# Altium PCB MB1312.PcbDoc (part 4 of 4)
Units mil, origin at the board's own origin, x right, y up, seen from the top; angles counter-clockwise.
Board outline 2755.91 x 5249.6 mil, 6 copper layers (Top Layer, GND, Signal, PWR, GND (Mid2), Bottom Layer), stack 74.545 mil thick; 297 components, 280 nets, 1142 pads, 623 vias.
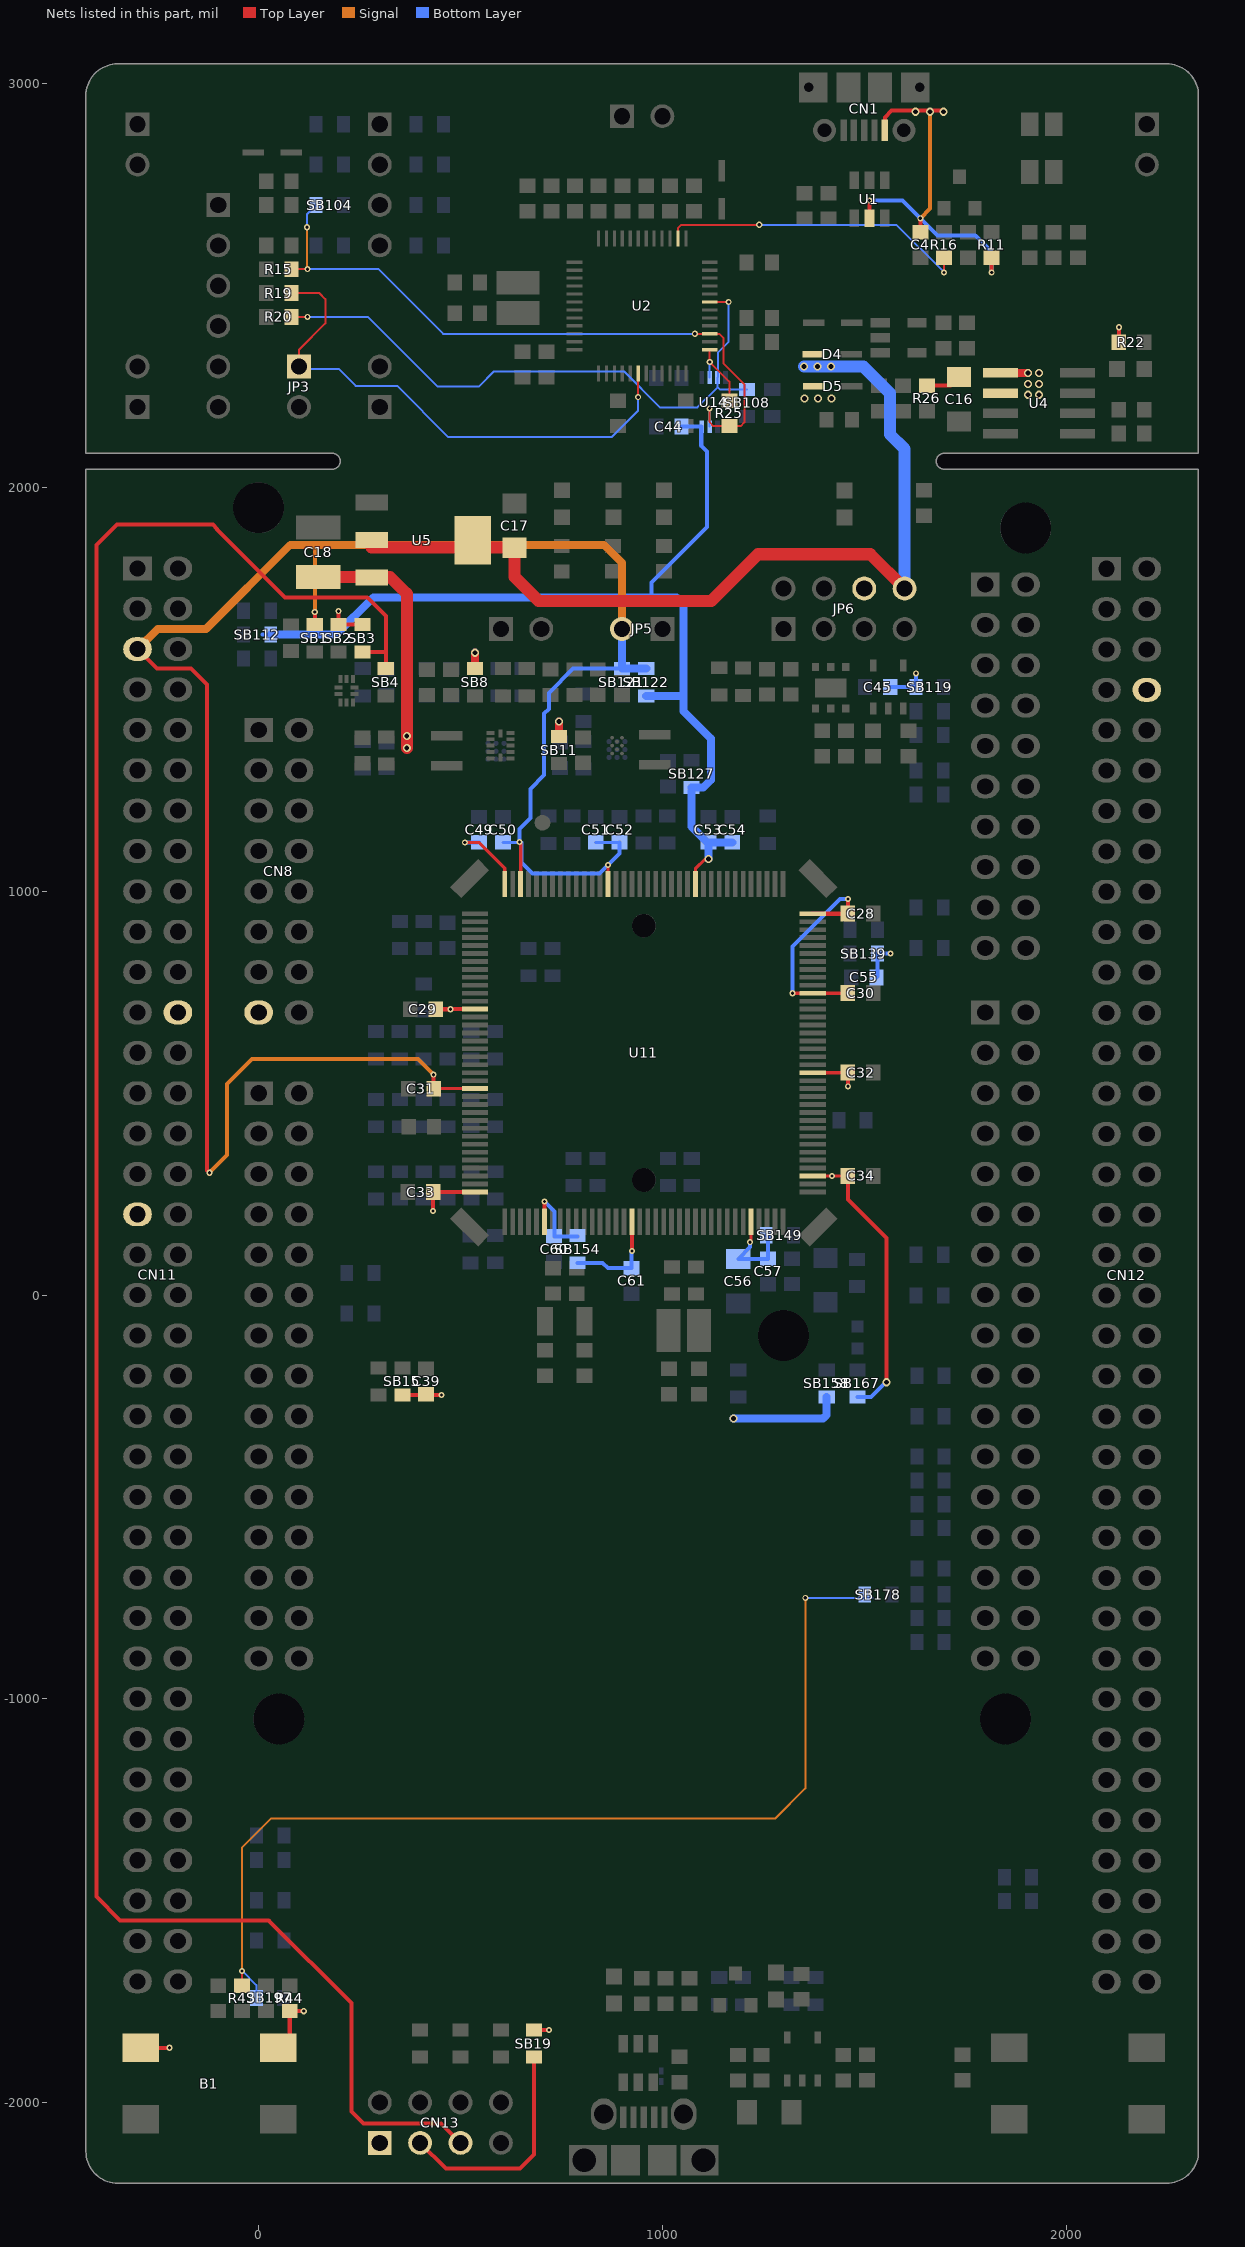
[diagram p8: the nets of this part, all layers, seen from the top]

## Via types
v1: diameter 15, hole 8, Top Layer to Bottom Layer, tented both sides, 405 vias
v2: diameter 16, hole 8, Top Layer to Bottom Layer, tented both sides, 179 vias
v3: diameter 20, hole 12, Top Layer to Bottom Layer, tented both sides, 39 vias

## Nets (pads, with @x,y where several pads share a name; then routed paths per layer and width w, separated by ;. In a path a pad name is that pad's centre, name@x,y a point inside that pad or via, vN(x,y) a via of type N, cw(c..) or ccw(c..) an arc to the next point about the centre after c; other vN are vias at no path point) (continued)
T_JTMS: R15.2 R25.2 SB104.1 U2.27 U14.7 | length 1711.1
  Top Layer w5: R15.2@81.5,2541 v1(121,2541) ; v1@1080.25,2381 v1(1080.35,2381.1) U2.27@1117.32,2381.1 1140.9,2381.1 1151,2371 1151,2308 1203,2256 1203,2161.47 1194.03,2152.5 R25.2@1166,2152.5 1126.5,2152.5 1117,2162 v1(1117,2196)
  Signal w5: v1@120,2542 v1(120,2645)
  Bottom Layer w5: v1(120,2645) 120,2677.75 SB104.1@142.25,2700 ; v1(121,2541) 297,2541 456.9,2381.1 v1(1080.35,2381.1) ; v1(1117,2196) 1117.16,2195.84 U14.7@1117.16,2150.98
T_NRST: JP3.1 R19.2 U2.18 | length 1318.5
  Top Layer w5: R19.2@81.5,2482 150,2482 165,2467 165,2407 100,2342 JP3.1@100,2300 ; v1(940,2224) 940.16,2224.16 U2.18@940.16,2282.68
  Bottom Layer w5: JP3.1@100,2300 100,2294.3 198.22,2294.3 240.37,2252.15 342.85,2252.15 470,2125 874,2125 940,2191 v1(940,2224)
T_SWDIO_IN: R25.1 U2.25 U14.2 | length 184.4
  Top Layer w5: U2.25@1117.32,2341.73 v1(1117.32,2310.97) 1166,2262.3 R25.1@1166,2215.5
  Bottom Layer w5: U14.2@1117.16,2273.02 1117.16,2310.81 v1(1117.32,2310.97)
T_SWO: R20.2 SB108.2 U2.31 U14.3 | length 1543.9
  Top Layer w5: R20.2@81.5,2423 v1(121,2423) ; U2.31@1117.32,2459.84 v1(1164.16,2459.84)
  Bottom Layer w5: v1(121,2423) 270.69,2423 442.69,2251 546,2251 583,2288 905,2288 994,2199 1086.84,2199 1136.84,2249 ; v1(1164.16,2459.84) 1164.16,2361.16 1137.32,2334.32 1137.32,2273.5 U14.3@1136.84,2273.02 1136.84,2249 ; SB108.2@1210,2243.5 1142.34,2243.5 1136.84,2249
U5V: C4.2 C16.1 CN1.1 CN12.8 D5.1 JP6.6 R11.2 R22.1 R26.1 U1.5 U4.1 U4.2 | length 1171.5
  Top Layer w10: U1.5@1513,2666.76 v1(1513,2711) ; CN1.1@1551.18,2885 1551.18,2917.18 1568,2934 v3@1696,2934 ; C4.2@1639,2632.5 v1(1639,2667) ; R26.1@1655,2252.5 1713.5,2252.5 C16.1@1735,2274 ; v1(1815.7,2533) R11.2@1815.7,2569.5 ; R22.1@2130.5,2360 v2@2130.5,2396.5
  Top Layer w20: U4.1@1837.53,2284 v3@1905.25,2284
  Signal w10: v1(1639,2667) 1663,2691 v3(1663,2931)
  Bottom Layer w10: v1(1513,2711) 1595,2711 v1(1639,2667) 1681,2625 1775,2625 1815.7,2584.3 v1@1815.7,2537.3 ; v3(1696,2931) v3@1696,2934
  other v2: 2131,2397
  other v3: 1352,2221 1385.5,2221 1419,2221 1906,2230 1933,2230 1906,2257 1933,2257 1906,2284 1933,2284 1627,2931
USB_RENUMN: R16.2 U2.38 | length 773.2
  Top Layer w5: U2.38@1038.58,2617.32 1038.58,2642.58 1047,2651 v2(1239.75,2651) ; v1(1697.7,2533) R16.2@1697.7,2569.5
  Bottom Layer w5: v2(1239.75,2651) 1579.7,2651 v1(1697.7,2533)
USR_BUT: R43.2 SB178.1 SB197.2 | length 2517.6
  Top Layer w5: R43.2@-41,-1710.5 v1(-41,-1674)
  Signal w5: v1(-41,-1674) -41,-1368 30,-1297 1279.06,-1297 1354.06,-1222 v1(1354.06,-750)
  Bottom Layer w5: v1(-41,-1674) -5.75,-1709.25 SB197.2@-5.75,-1741 ; v1(1354.06,-750) 1520,-750
VBAT: C60.1 CN11.33 SB154.2 U11.6 | length 204.2
  Top Layer w10: U11.6@707.94,181.69 v1(707.94,231.94)
  Bottom Layer w10: v1(707.94,231.94) 733.25,206.62 733.25,145.25 SB154.2@790,145.25
VDD: C31.1 C50.1 C51.1 C52.1 CN11.5 CN13.1 JP5.2 SB1.2 SB8.2 SB121.1 SB122.1 SB158.1 U11.95 U11.106 U11.131 | length 5734.1
  Top Layer w8: C31.1@434.08,511.42 U11.131@535.69,511.42 ; v1(646,1122) 649.48,1118.52 U11.106@649.48,1018.91 ; U11.106@648.2,1020.19 U11.106@649.48,1018.91 ; U11.106@648.88,1018.31 U11.106@649.48,1018.91 ; U11.95@865.42,1018.31 v1(865.42,1065.58)
  Top Layer w10: CN11.5@-300,1600 -251.5,1551.5 -167,1551.5 -128,1512.5 -128,309 v1(-122,303) ; SB1.2@139,1660.75 v1(139,1691.75) ; v1@433,546.01 433.5,546.5 C31.1@433.5,511 ; U11.131@535.11,512 U11.131@535.69,511.42
  Top Layer w20: SB8.2@536,1551.5 v3(536,1591)
  Signal w10: v1@-122,300 v1(-122,303) -78,347 -78,523 -16.55,584.45 394.55,584.45 v1(433,546) ; v1(139,1691.75) 139,1856.12
  Signal w20: CN11.5@-300,1600 -250,1650 -130,1650 78.4,1858.4 855.6,1858.4 900,1814 JP5.2@900,1650
  Bottom Layer w8: C50.1@605,1121.25 v1@649.48,1121.25 ; C51.1@835,1121.25 C52.1@894,1121.25
  Bottom Layer w10: C52.1@894,1121.25 894,1094.17 v1(865.42,1065.58) 844.33,1044.5 677.92,1044.5 650.48,1071.94 650.48,1120.52 649,1122 v1(646,1122) 646,1155 673,1182 673,1253.81 707,1287.81 707,1440 719,1452 719,1491.75 779,1551.75 SB121.1@899.79,1551.75 SB121.1@900.21,1551.75
  Bottom Layer w20: JP5.2@900,1650 900,1551.96 900.21,1551.75 SB122.1@960,1551.75 ; v3(1176,-306.03) 1397.97,-306.03 1407,-297 SB158.1@1407,-252.75
VDD_1V2: C39.2 C55.2 SB2.2 SB3.1 SB11.2 SB15.2 SB139.2 | length 318.4
  Top Layer w10: SB2.2@197.77,1660.81 v1@197.77,1693.87 ; SB2.2@197.83,1660.75 SB3.1@257,1660.75 ; SB15.2@356,-247.75 v1(453,-247.75)
  Top Layer w20: SB11.2@744,1383.75 v3(744,1421)
  Bottom Layer w10: C55.2@1530.5,787 1532.75,789.25 SB139.2@1532.75,846 v1(1564.75,846)
  other v1: 197.83,1693.92
VDD_MCU: B1.2 B1.3 C28.1 C29.1 C30.1 C32.1 C33.1 C34.1 C44.1 C49.1 C53.1 C54.1 C61.1 R44.1 SB19.2 SB112.1 SB122.2 SB127.2 SB154.1 SB167.1 U11.17 U11.39 U11.52 U11.62 U11.72 U11.84 U11.108 U11.121 U11.144 U14.8 | length 4914.8
  Top Layer w8: v1(510.57,1121.25) 545.53,1121.25 609.51,1057.27 U11.108@609.51,1018.31 ; U11.84@1081.95,1018.31 1081.95,1056.33 1105.62,1080 v3(1114,1080) ; v1(1322.26,747.64) U11.62@1372.31,747.64 C30.1@1459.14,747.64 ; U11.39@1372.31,294.88 v1(1419.88,294.88) ; U11.52@1372.31,550.79 C32.1@1459.29,550.79 ; v1@1419.88,295 C34.1@1459.5,295
  Top Layer w10: B1.2@-292.28,-1864.42 v1(-220.58,-1864.42) ; B1.3@48.28,-1864.42 77,-1835.69 R44.1@77,-1773.5 v2(111.5,-1773.5) ; v1(432,208) 432,254.5 C33.1@432.5,255 433.01,255.51 U11.144@535.69,255.51 ; C29.1@438.5,708 v1(475,708) ; v1@475,708.27 U11.121@535.69,708.27 ; SB19.2@682,-1820.25 v1(719.05,-1820.25) ; v1(924.47,109) U11.17@924.47,181.69 ; U11.72@1372.31,944.49 1455.98,944.49 1458,946.5 C28.1@1459.5,945 v1(1459.5,981) ; C30.1@1459.14,747.64 C30.1@1459.5,748 ; C32.1@1459.29,550.79 C32.1@1459.5,551 1460,550.5 v1(1460,517) ; C34.1@1459.5,295 1459.5,236.5 1555,141 1555,-16 v3(1555,-216)
  Bottom Layer w10: 10,1636 SB112.1@30,1636 ; v1(510.57,1121.25) C49.1@546,1121.25 ; SB154.1@790,80 852,80 865.5,66.5 C61.1@924,66.5 924,108.53 v1(924.47,109) ; 973,1728 973,1765 1110,1902 1110,2090 1096.25,2103.75 1096.25,2150.98 C44.1@1047.5,2151 ; v1(1322.26,747.64) 1322.26,863.01 1440.25,981 v1(1459.5,981) ; SB167.1@1483,-252.75 1516.25,-252.75 1553,-216 v3(1555,-216)
  Bottom Layer w20: SB112.1@30,1636 192,1636 284,1728 973,1728 1035,1728 1052,1711 1052,1446.16 1120,1378.16 1120,1276 1101.31,1257.31 SB127.2@1072.47,1257.31 ; SB122.2@960,1484.25 1050,1484.25 ; SB127.2@1072,1248.5 1072,1160.56 1111.31,1121.25 C53.1@1114,1121.25 ; v3(1114,1080) C53.1@1114,1121.25 ; C54.1@1173,1121.25 C53.1@1114,1121.25
VIN: C18.1 CN8.15 CN11.24 U5.3 | length 618.4
  Top Layer w30: C18.1@148,1778.98 325.02,1778.98 367,1737 v3(367,1355)
  other v3: 367,1385
VIN_5V: C17.1 D4.1 JP6.8 U5.2 U5.4 | length 2239.9
  Top Layer w30: U5.2@280,1852 633,1852 C17.1@634,1851 634,1778.47 693.47,1719 1121,1719 1237,1835 1515,1835 JP6.8@1600,1750
  Bottom Layer w30: v3(1351,2300) v3(1384.5,2300) v3(1418,2300) 1497.71,2300 1563.5,2234.21 1563.5,2132.25 1600,2095.75 JP6.8@1600,1750
VOUTCORE: CN13.5 SB3.2 SB4.2 | length 5679.8
  Top Layer w10: SB3.2@257,1593.25 314.75,1593.25 ; SB4.2@315,1551.5 315,1682 269,1728 65,1728 -103.29,1896.29 -103.29,1897.85 -113.54,1908.1 -351.25,1908.1 -402,1857.35 -402,-1490 -343,-1549 25,-1549 230,-1754 230,-2022 260,-2052 452,-2052 CN13.5@500,-2100
VOUTVDD: CN13.3 SB19.1 | length 564.3
  Top Layer w10: CN13.3@400,-2100 464,-2164 647,-2164 682,-2129 SB19.1@682,-1887.75
VREF+: C45.1 C56.1 C57.1 SB119.1 SB149.2 U11.32 | length 337.6
  Top Layer w8: v1(1217,131) 1219.75,133.75 U11.32@1219.75,181.69
  Bottom Layer w10: v1(1217,131) 1217,118.5 C56.1@1188,89.5 1261.5,89.5 1261.5,143.75 SB149.2@1257.25,148 ; C45.1@1564.75,1506 SB119.1@1628.5,1506 1628.5,1539.5 v1(1628,1540) v1@1628.39,1540.39
pads on no net: CN8.1 CN11.10 CN11.26 CN11.67 U2.4 U2.11 U2.14 U2.19 U2.21 U2.22 U2.40 U2.41 U2.42 U2.43 U2.45 U2.46 U6.3 U6.5 U7.1 U7.6 U10.E1 U11.0 U16.C1
copper on no net:
  other v1: 1115.9,2629

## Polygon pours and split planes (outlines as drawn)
GND on Top Layer "GND" (solid, remove dead copper, pour order 268): -430.95,-2118.26 ccw(c-352.21,-2118.26) -352.21,-2197 -352.21,-2197.04 45,-2197.04 1040.41,-2197.04 2246.06,-2197.04 ccw(c2246.06,-2118.3) 2324.8,-2118.3 2324.8,-2118.1 2324.95,-2118.1 2324.95,2973.87 ccw(c2246.21,2973.87) 2246.21,3052.61 -352.21,3052.61 ccw(c-352.21,2973.87) -430.95,2973.87 -430.95,-2118.26
NetL1_1 on Top Layer "NETL301" (solid, remove dead copper, pour order 248): 567,1366.69 583.36,1366.69 cw(c583.36,1364.05) 586,1364.05 586,1357.21 cw(c584.96,1357.21) 584.96,1356.17 517.25,1356.17 cw(c517.25,1361.25) 512.17,1361.25 512.17,1364.83 ccw(c504,1364.83) 504,1373 399.17,1373 cw(c399.17,1382) 390.17,1382 390.17,1414.76 cw(c396.41,1414.76) 396.41,1421 501.98,1421 cw(c501.98,1417.53) 505.45,1417.53 505.45,1398.64 ccw(c506.85,1398.64) 506.85,1397.24 551,1366.69
NetC21_2 on Top Layer "NETL308" (solid, remove dead copper, pour order 246): 253,1335 346,1335 cw(c346,1331) 350,1331 ccw(c359,1331) 359,1322 435,1322 550.18,1322 ccw(c550.18,1329) 557.18,1329 cw(c562.18,1329) 562.18,1334 566,1334 579.96,1334 cw(c579.96,1329) 584.96,1329 584.96,1286.96 cw(c573,1286.96) 573,1275 245,1275 cw(c245,1287) 233,1287 233,1329.17 cw(c238.83,1329.17) 238.83,1335
NetC22_2 on Top Layer "NETL306" (solid, remove dead copper, pour order 242): 400,1504 488.73,1504 546,1504 cw(c546,1494) 556,1494 556,1389 ccw(c563,1389) 563,1382 583,1382 cw(c583,1379) 586,1379 586,1373.05 cw(c583.95,1373.05) 583.95,1371 556,1371 556,1371.24 555.27,1371.97 551,1371.97 544.23,1371.97 520.36,1395.85 512.53,1403.67 512.53,1410 512.25,1410 512.25,1424 512.25,1459 ccw(c508.24,1459) 508.24,1463.01 402.99,1463.01 cw(c402.99,1471) 395,1471 395,1503 cw(c396,1503) 396,1504
NetL1_1 on Top Layer "NETL301" (solid, remove dead copper, pour order 240): 584.2,1365.85 cw(c584.2,1364.05) 586,1364.05 586,1362 586,1357.82 cw(c584.18,1357.82) 584.18,1356 531.71,1356 cw(c531.71,1361) 526.71,1361 ccw(c514.82,1361) 514.82,1372.89 509,1372.89 396.32,1372.89 cw(c396.32,1379.21) 390,1379.21 390,1413 cw(c398,1413) 398,1421 500,1421 cw(c500,1415) 506,1415 506,1400.04 ccw(c511.04,1400.04) 511.04,1395 550,1365.85
NetC46_2 on Top Layer "SB368" (solid, remove dead copper, pour order 236): 594.54,1344.39 604.37,1344.39 cw(c604.37,1340.99) 607.76,1340.99 607.76,1312.18 ccw(c613.83,1312.18) 613.83,1306.12 694.12,1306.12 ccw(c694.12,1312) 700,1312 700,1331.24 cw(c705.01,1331.24) 705.01,1336.25 763.16,1336.25 cw(c763.16,1331.41) 768,1331.41 768,1293.5 cw(c757.83,1293.5) 757.83,1283.33 598.88,1283.33 cw(c598.88,1290.21) 592,1290.21 592,1341.86 cw(c594.54,1341.86) 594.54,1344.39
NetC24_1 on Top Layer "304" (solid, remove dead copper, pour order 204): 820,1506.75 cw(c822.25,1506.75) 822.25,1509 908.79,1509 919.74,1509 cw(c919.74,1504) 924.74,1504 924.74,1459.49 cw(c921.25,1459.49) 921.25,1456 918.18,1456 ccw(c918.18,1450) 912.18,1450 912.18,1389.18 cw(c888,1389.18) 888,1365 887,1365 cw(c887,1371) 881,1371 881,1448.26 ccw(c870.26,1448.26) 870.26,1459 825,1459 cw(c825,1464) 820,1464
NetL2_1 on Top Layer "300" (solid, remove dead copper, pour order 202): 900,1366 ccw(c900,1361) 895,1361 ccw(c900,1361) 900,1356 911.25,1356 ccw(c911.25,1358) 913.25,1358 cw(c921.25,1358) 921.25,1366 922,1366 1017.98,1366 ccw(c1017.98,1371.25) 1023.23,1371.25 1023.23,1420.77 ccw(c1017,1420.77) 1017,1427 926,1427 ccw(c926,1421) 920,1421 920,1390.92 cw(c919.08,1390.92) 919.08,1390 900,1366
NetC47_2 on Top Layer "304" (solid, remove dead copper, pour order 200): 908,1346 895,1346 ccw(c895,1343) 892,1343 892,1306 ccw(c899,1306) 899,1299 1021,1299 ccw(c1021,1302) 1024,1302 1024,1342 ccw(c1017,1342) 1017,1349 941,1349 ccw(c941,1345) 937,1345 937,1344.4 cw(c930.6,1344.4) 930.6,1338 916,1338 cw(c916,1346) 908,1346
NetC21_2 on Bottom Layer "NETL308" (solid, remove dead copper, pour order 252): 433.3,1305.76 427.65,1305.76 ccw(c427.65,1300.55) 422.44,1300.55 422.44,1274.81 ccw(c428.28,1274.81) 428.28,1268.97 575.49,1268.97 ccw(c575.49,1290.76) 597.28,1290.76 597.28,1328.48 ccw(c591.76,1328.48) 591.76,1334 585.04,1334 ccw(c585.04,1329.4) 580.44,1329.4 580.44,1309.92 cw(c574.6,1309.92) 574.6,1304.08 431.29,1304.08 ccw(c431.29,1294.81) 422.01,1294.81
NetL2_1 on Bottom Layer "300" (solid, remove dead copper, pour order 158): 948.29,1427.3 1016.09,1427.3 cw(c1016.09,1421.39) 1022,1421.39 1022,1394.4 cw(c1016,1394.4) 1016,1388.4 942.4,1388.4 ccw(c942.4,1383) 937,1383 937,1372 cw(c929,1372) 929,1364 904,1364 cw(c904,1369) 899,1369 899,1379.82 cw(c899.97,1379.82) 899.97,1380.78 910.87,1380.78 ccw(c910.87,1389) 919.08,1389 919.08,1416.33 cw(c930.01,1416.33) 930.01,1427.26
NetC24_1 on Bottom Layer "300" (solid, remove dead copper, pour order 159): 786,1504.25 907.29,1504.25 cw(c907.29,1491.75) 919.79,1491.75 919.79,1452.79 cw(c911,1452.79) 911,1444 ccw(c911,1431) 898,1431 898,1393.21 898,1369.11 cw(c893,1369.11) 893,1364.11 860.83,1364.11 cw(c860.83,1365.94) 859,1365.94 859,1457 ccw(c846,1457) 846,1470 796,1470 cw(c796,1481) 785,1481
NetL1_1 on Bottom Layer "304" (solid, remove dead copper, pour order 184): 601,1369 601,1361 ccw(c602,1361) 602,1360 624.75,1360 ccw(c624.75,1363.25) 628,1363.25 628,1392.61 ccw(c623,1392.61) 623,1397.61 617.52,1397.61 cw(c617.52,1401.12) 614,1401.12 614,1448.19 ccw(c608.19,1448.19) 608.19,1454 428.07,1454 ccw(c428.07,1447.81) 421.88,1447.81 421.88,1395.55 ccw(c433,1395.55) 433,1384.44 508.44,1384.44 ccw(c508.44,1392) 516,1392 516,1420.48 cw(c528.52,1420.48) 528.52,1433 565,1433 cw(c565,1425) 573,1425 595.53,1391 599,1378
NetC47_2 on Bottom Layer "303" (solid, remove dead copper, pour order 216): 880,1335 879,1334 879,1328
NetC47_2 on Bottom Layer "303" (solid, remove dead copper, pour order 218): 879,1324.81 879,1336 cw(c882,1336) 882,1339 891.5,1339 cw(c891.5,1334.5) 896,1334.5 896,1324.55 ccw(c898,1324.55) 898,1322.55 937.55,1322.55 ccw(c937.55,1326) 941,1326 941,1353 cw(c948,1353) 948,1360 1083,1360 cw(c1083,1349) 1094,1349 1094,1306.33 cw(c1092.47,1306.33) 1092.47,1304.81 881.19,1304.81 cw(c881.19,1307) 879,1307
GND on Bottom Layer "GND" (solid, remove dead copper, pour order 262): -423.96,-2121.26 ccw(c-345.22,-2121.26) -345.22,-2200 -345.22,-2200.04 51.99,-2200.04 1047.4,-2200.04 2253.05,-2200.04 ccw(c2253.05,-2121.3) 2331.79,-2121.3 2331.79,-2121.1 2331.94,-2121.1 2331.94,2970.87 ccw(c2253.2,2970.87) 2253.2,3049.61 -345.22,3049.61 ccw(c-345.22,2970.87) -423.96,2970.87 -423.96,-2121.26
GND on Signal "GND" (solid, remove dead copper, pour order 156): -427.95,-2121.26 ccw(c-349.21,-2121.26) -349.21,-2200 -349.21,-2200.04 48,-2200.04 1043.41,-2200.04 2249.06,-2200.04 ccw(c2249.06,-2121.3) 2327.8,-2121.3 2327.8,-2121.1 2327.95,-2121.1 2327.95,2970.87 ccw(c2249.21,2970.87) 2249.21,3049.61 -349.21,3049.61 ccw(c-349.21,2970.87) -427.95,2970.87 -427.95,-2121.26
GND on GND "GND" (solid, remove dead copper, pour order 142): -427.95,-2121.26 ccw(c-349.21,-2121.26) -349.21,-2200 -349.21,-2200.04 48,-2200.04 1043.41,-2200.04 2249.06,-2200.04 ccw(c2249.06,-2121.3) 2327.8,-2121.3 2327.8,-2121.1 2327.95,-2121.1 2327.95,2970.87 ccw(c2249.21,2970.87) 2249.21,3049.61 -349.21,3049.61 ccw(c-349.21,2970.87) -427.95,2970.87 -427.95,-2121.26
U5V on PWR "U5V" (solid, remove dead copper, pour order 266): 1804,2246.47 1371.47,2246.47 ccw(c1371.47,2201) 1326,2201 1326,2081.52 ccw(c1358.52,2081.52) 1358.52,2049 1440.91,2049 cw(c1440.91,2026) 1463.91,2026 1463.91,1632.84 ccw(c1490,1632.84) 1490,1606.74 1683.69,1606.74 cw(c1683.69,1581.39) 1709.04,1581.39 1709.04,1381.76 ccw(c1735,1381.76) 1735,1355.8 2299.8,1355.8 ccw(c2299.8,1370) 2314,1370 2314,2980 ccw(c2254,2980) 2254,3040 1507.05,3040 ccw(c1507.05,3007.95) 1475,3007.95 1475,2850.57 ccw(c1500.57,2850.57) 1500.57,2825 2015,2825 cw(c2015,2725) 2115,2725 2115,2712 2115,2309.51 cw(c2102.51,2309.51) 2102.51,2297.02 1885.48,2297.02 ccw(c1885.48,2281.54) 1870,2281.54 1870,2263.47 cw(c1853,2263.47) 1853,2246.47
NetC11_2 on PWR "netc11_2" (solid, remove dead copper, pour order 264): 1338,2346.79 1195.34,2346.79 ccw(c1195.34,2321) 1169.55,2321 1169.55,1993.05 ccw(c1194.6,1993.05) 1194.6,1968 1330,1968 cw(c1330,1942) 1356,1942 1356,1621 ccw(c1368,1621) 1368,1609 1442.85,1609 ccw(c1442.85,1615.47) 1449.32,1615.47 1449.32,2050.68 ccw(c1410,2050.68) 1410,2090 1329.21,2090 cw(c1329.21,2106) 1313.21,2106 1313.21,2222.8 cw(c1343.36,2222.8) 1343.36,2252.95 1837.95,2252.95 ccw(c1837.95,2277) 1862,2277 1862,2292.43 cw(c1877,2292.43) 1877,2307.43 2082.93,2307.43 ccw(c2082.93,2337) 2112.5,2337 2112.5,2367.46 ccw(c2097.83,2367.46) 2097.83,2382.13 1482.96,2382.13 ccw(c1482.96,2359) 1459.83,2359 cw(c1448.07,2359) 1448.07,2347.25 1438,2347.25
VDD_MCU on PWR "VDDIO" (solid, remove dead copper, pour order 155): 496.27,1394 1151.3,1394 cw(c1151.3,1373) 1172.3,1373 1172.3,872.7 ccw(c1221,872.7) 1221,824 1439.6,824 cw(c1439.6,791) 1472.6,791 1472.6,325.78 cw(c1430,325.78) 1430,283.18 1035.47,283.18 ccw(c1035.47,259.71) 1012,259.71 1012,-148 cw(c956,-148) 956,-204 365.18,-204 ccw(c365.18,-224.18) 345,-224.18 345,-259.71 ccw(c362.29,-259.71) 362.29,-277 1118.68,-277 cw(c1118.68,-299) 1140.68,-299 1140.68,-1877 cw(c1040.68,-1877) 1040.68,-1977 1003,-1977 -396,-1977 cw(c-396,-1947) -426,-1947 -426,-33 cw(c-393,-33) -393,0 696.75,0 ccw(c696.75,35.25) 732,35.25 732,248.31 ccw(c710.31,248.31) 710.31,270 603.29,270 ccw(c603.29,259.71) 593,259.71 593,153.55 cw(c575,153.55) 575,135.55 306.45,135.55 cw(c306.45,156) 286,156 286,579 cw(c309,579) 309,602 456.63,602 ccw(c456.63,624.37) 479,624.37 479,1378 cw(c495,1378) 495,1394
VIN on PWR "VIN" (solid, remove dead copper, pour order 154): -393,1043 -393,1043.38 42.6,1043.38 158.9,1043.38 ccw(c158.9,1059.1) 174.62,1059.1 174.62,1348.05 cw(c215.57,1348.05) 215.57,1389 436.26,1389 cw(c436.26,1356.52) 468.74,1356.52 468.74,627.58 cw(c451,627.58) 451,609.84 -388.73,609.84 cw(c-388.73,637.44) -416.33,637.44 -416.33,1037.71 cw(c-411.04,1037.71) -411.04,1043
VDD on PWR "VDD" (solid, remove dead copper, pour order 152): 477,1754.74 918.16,1754.74 cw(c918.16,1731) 941.9,1731 941.9,1616.7 ccw(c962.6,1616.7) 962.6,1596 1412.99,1596 cw(c1412.99,1560.82) 1448.17,1560.82 1448.17,1044.42 ccw(c1482.59,1044.42) 1482.59,1010 1610.53,1010 cw(c1610.53,989.53) 1631,989.53 1631,176.82 cw(c1612.18,176.82) 1612.18,158 1221,158 ccw(c1221,136) 1199,136 1199,-2193 cw(c1190,-2193) 1190,-2202 -354,-2202 cw(c-354,-2130) -426,-2130 -426,-2011 cw(c-401,-2011) -401,-1986 1046.57,-1986 ccw(c1046.57,-1886) 1146.57,-1886 1146.57,-244.4 1146.57,135.57 cw(c1212,135.57) 1212,201 1551.56,201 ccw(c1551.56,237.44) 1588,237.44 1588,879.09 ccw(c1534.53,879.09) 1534.53,932.57 1372.12,932.57 cw(c1372.12,972.4) 1332.28,972.4 1332.28,1487.18 ccw(c1298.08,1487.18) 1298.08,1521.37 472.75,1521.37 cw(c472.75,1523.15) 470.98,1523.15 cw(c470.98,1550.93) 443.2,1550.93 443.2,1567.63 443.2,1725.2 cw(c473,1725.2) 473,1755
VDD_1V2 on PWR "VDD1V2" (solid, remove dead copper, pour order 151): 225.88,1750 415.82,1750 cw(c415.82,1722.62) 443.2,1722.62 443.2,1553.8 ccw(c474,1553.8) 474,1523 1285.28,1523 cw(c1285.28,1476) 1332.28,1476 1332.28,958.72 ccw(c1363,958.72) 1363,928 1540.2,928 cw(c1540.2,888.4) 1579.8,888.4 1579.8,234.8 cw(c1553,234.8) 1553,208 1185.8,208 ccw(c1185.8,170) 1147.8,170 1147.8,-235.1 cw(c1115.9,-235.1) 1115.9,-267 371.68,-267 cw(c371.68,-254) 358.68,-254 358.68,-220.14 cw(c367,-220.14) 367,-211.82 980.18,-211.82 ccw(c980.18,-175) 1017,-175 1017,224.63 cw(c1055.09,235.31) 1044.4,273.4 1453,273.4 ccw(c1464.49,289.91) 1481,278.43 1481,791 ccw(c1441,791) 1441,831 1223,831 cw(c1223,874) 1180,874 1180,1389.72 ccw(c1168.72,1389.72) 1168.72,1401 215,1401 cw(c215,1441) 175,1441 175,1724 cw(c201,1724) 201,1750
VBAT on PWR "VBAT" (solid, remove dead copper, pour order 150): 268,572.37 ccw(c245.37,572.37) 245.37,595 229.43,595 -394,595 ccw(c-394,566) -423,566 -423,26 ccw(c-407,26) -407,10 695.9,10 ccw(c695.9,38) 723.9,38 723.9,246.67 ccw(c708,246.67) 708,262.56 606.87,262.56 ccw(c606.87,259) 603.31,259 603.31,148.71 cw(c580.6,148.71) 580.6,126 283.23,126 cw(c283.23,131.23) 278,131.23 278,575.55 ccw(c263,575.55) 263,590.55
E5V on PWR "E5V" (solid, remove dead copper, pour order 147): 915,2043 -408,2043 ccw(c-408,2026) -425,2026 -425,1572.31 ccw(c-407.69,1572.31) -407.69,1555 -117.3,1555 ccw(c-117.3,1581.69) -90.61,1581.69 -90.61,1802.66 cw(c-63.27,1802.66) -63.27,1830 95,1830 ccw(c95,1847) 112,1847 112,1850.84 cw(c139.16,1850.84) 139.16,1878 1223,1878 cw(c1223,1858) 1243,1858 1243,1618.89 ccw(c1257.13,1615.94) 1254.19,1601.81 1339,1601.81 ccw(c1334.78,1614.03) 1347,1618.26 1347,1937.96 ccw(c1327.96,1937.96) 1327.96,1957 1178.27,1957 cw(c1178.27,1976.04) 1159.23,1976.04 1159.23,2325.93 cw(c1189,2325.93) 1189,2355.7 1437.98,2355.7 ccw(c1437.98,2367.72) 1450,2367.72 1450,2422.82 ccw(c1437.82,2422.82) 1437.82,2435 1117.66,2435 ccw(c1117.66,2413) 1095.66,2413 1095.66,2047.66 cw(c1091,2047.66) 1091,2043
+3V3 on PWR "3V3" (solid, remove dead copper, pour order 146): -166,1549 -410.3,1549 ccw(c-410.3,1534.3) -425,1534.3 -425,1078 ccw(c-399,1078) -399,1052 144.41,1052 ccw(c144.41,1072.59) 165,1072.59 165,1704.88 cw(c226.12,1704.88) 226.12,1766 925.97,1766 cw(c925.97,1743.65) 948.32,1743.65 948.32,1622.03 ccw(c966.35,1622.03) 966.35,1604 1213.5,1604 ccw(c1213.5,1625.5) 1235,1625.5 1235,1856.66 ccw(c1219.66,1856.66) 1219.66,1872 144.26,1872 ccw(c144.26,1847) 119.26,1847 119.26,1842.95 cw(c100.74,1842.95) 100.74,1824.44 -59.43,1824.44 ccw(c-59.43,1798.87) -85,1798.87 -85,1577 cw(c-113,1577) -113,1549
+3V3_ST_LINK on PWR "ST_3V3" (solid, remove dead copper, pour order 143): -335,3037 -353,3037 ccw(c-353,2975) -415,2975 -415,2107 ccw(c-406,2107) -406,2098 1080.53,2098 ccw(c1080.53,2104.47) 1087,2104.47 1087,2418.35 cw(c1109.65,2418.35) 1109.65,2441 1443.76,2441 cw(c1443.76,2428.46) 1456.3,2428.46 1456.3,2396.7 ccw(c1463,2396.7) 1463,2390 2096.07,2390 ccw(c2096.07,2399) 2105.07,2399 2105.07,2714 ccw(c2005.07,2714) 2005.07,2814 1996,2814 1488,2814 cw(c1488,2832) 1470,2832 1470,3022.06 ccw(c1455,3022.06) 1455,3037.06 -335,3037.06
VREF+ on PWR "REFER" (solid, remove dead copper, pour order 226): 1485.32,1602 1661.57,1602 cw(c1661.57,1570) 1693.57,1570 1693.57,109.07 cw(c1683.5,109.07) 1683.5,99 1213.63,99 cw(c1213.63,110) 1202.63,110 1202.63,135.63 cw(c1220,135.63) 1220,153 1618.74,153 ccw(c1618.74,170) 1635.74,170 1635.74,996.26 ccw(c1615,996.26) 1615,1017 1479.61,1017 cw(c1479.61,1044) 1452.61,1044 1452.61,1581.61 cw(c1473,1581.61) 1473,1602
AVDD on PWR "AVDD" (solid, remove dead copper, pour order 228): 1752,797.4 1949.6,797.4 cw(c1949.6,775) 1972,775 1972,669 cw(c1963,669) 1963,660 1768,660 ccw(c1768,637) 1745,637 1745,563.55 ccw(c1763.55,563.55) 1763.55,545 1826,545 cw(c1826,522) 1849,522 1849,38.27 cw(c1797,38.27) 1797,-13.73 1213.36,-13.73 cw(c1213.36,-3) 1202.63,-3 1202.63,79.36 cw(c1214,79.36) 1214,90.73 1690.23,90.73 ccw(c1690.23,102.5) 1702,102.5 1702,772 cw(c1728,772) 1728,798
AGND on PWR "AGND" (solid, remove dead copper, pour order 230): 1742,1344.24 2286.76,1344.24 cw(c2286.76,1313) 2318,1313 2318,-2121 cw(c2247,-2121) 2247,-2192 1236.73,-2192 cw(c1236.73,-2163.27) 1208,-2163.27 1208,-36 cw(c1222,-36) 1222,-22 1798,-22 ccw(c1798,35) 1855,35 1855,534.28 ccw(c1836,534.28) 1836,553.28 1769.43,553.28 cw(c1769.43,570) 1752.72,570 1752.72,629.81 cw(c1776.18,629.81) 1776.18,653.27 1962.27,653.27 ccw(c1962.27,673) 1982,673 1982,776 ccw(c1953,776) 1953,805 1727.75,805 cw(c1727.75,829.75) 1703,829.75 1703,1302.27 cw(c1744,1302.27) 1744,1343.27
GND on GND (Mid2) "GND" (solid, remove dead copper, pour order 140): -427.95,-2121.26 ccw(c-349.21,-2121.26) -349.21,-2200 -349.21,-2200.04 48,-2200.04 1043.41,-2200.04 2249.06,-2200.04 ccw(c2249.06,-2121.3) 2327.8,-2121.3 2327.8,-2121.1 2327.95,-2121.1 2327.95,2970.87 ccw(c2249.21,2970.87) 2249.21,3049.61 -349.21,3049.61 ccw(c-349.21,2970.87) -427.95,2970.87 -427.95,-2121.26

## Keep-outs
Keep-Out Layer:
  lines w5: -349.37,-2200.04 1040,-2200.04 ; -349.21,-2200 cw(c-349.21,-2121.26) -427.95,-2121.26 -427.95,2045.67 182.28,2045.67 ccw(c182.28,2065.35) 182.28,2085.04 -427.95,2085.04 -427.95,2970.87 cw(c-349.21,2970.87) -349.21,3049.61 2249.21,3049.61 cw(c2249.21,2970.87) 2327.95,2970.87 ; 1598,-2200.04 2249.06,-2200.04 ; 2249.06,-2199.84 ccw(c2249.06,-2121.1) 2327.8,-2121.1 ; 2327.95,-2121.26 2327.95,2045.67 1698.03,2045.67 cw(c1698.03,2065.35) 1698.03,2085.04 2327.95,2085.04 2327.95,2970.87 ; 2327.95,2970.87 2327.95,2970.87 ; 320.08,2045.67 cw(c320.08,2065.35) 320.08,2085.04 1068.11,2085.04 cw(c1068.11,2065.35) 1068.11,2045.67 320.08,2045.67 ; 1250,2045.67 cw(c1250,2065.35) 1250,2085.04 1538.58,2085.04 cw(c1538.58,2065.35) 1538.58,2045.67 1250,2045.67

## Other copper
Top Layer:
  rectangle net U5V: 1341,2209 1431,2264
  rectangle net E5V: 1341,2366 1431,2421
  rectangle net NetC11_2: 1957,2330 2071,2384
  rectangle net U5V: 1703,2216 1946,2300
  rectangle net +3V3_ST_LINK: 1606,2386 1843,2436.06
  rectangle net VIN_5V: 1340,2288 1430,2343
  pour cut-out: 1775,2169 1784.22,2169 1784.22,2175 1775,2175
  pour cut-out: 1695,2169 1695,2176 1684.53,2176 1684.53,2169
GND:
  pour cut-out: 1009,-1093.17 1009,-1503 1384.68,-1503 1384.68,-1093 1383,-1093
GND (Mid2):
  pour cut-out: 1009,-1093.17 1009,-1503 1384.68,-1503 1384.68,-1093 1383,-1093

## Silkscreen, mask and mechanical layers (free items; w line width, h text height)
Top Overlay:
  drawing of 1972 lines, arcs and shapes, not listed
  text "USB PWR" at 1256,3034 h40 r270
  text "GND" at -227,2916 h40 r270
  text "COM" at 1819,2906 h60 r270
  text "GND" at 2088,2899.94 h40 r270
  text "ST-LINK" at 127,2825 h40 r270
  text "NUCLEO" at 434,2825 h40 r270
  text "SWD" at -220,2567 h40 r270
  text "STLK_RST" at -417,2385 h36
  text "MCU_RST" at 185,2338 h36 r270
  text "TX" at 368,2282 h40
  text "Over Current" at 2087,2229 h40
  text "RX" at 369,2182 h40
  text "User LEDs" at 1133,2023 h40 r270
  text "PWR" at 1368,2014 h40 r270
  text "E5V" at 1219.75,1817 h40
  text "STLK" at 1335,1817 h40
  text "CHGR" at 1472,1817 h40
  text "VIN" at 1632.25,1816 h40
  text "SCL" at 1958.06,1773 h45
  text "USB_IO" at 546,1723 h40
  text "D15" at 1962,1719 h40
  text "IDD" at 912.7,1718 h40
  text "PG5" at 767,1696 h40 r270
  text "SDA" at 1958.06,1669 h45
  text "I2S_A" at 1673,1659 h40 r270
  text "D14" at 1962,1618 h40
  text "VREF+" at 1965,1533 h30
  text "GND" at 1962,1438 h40
  text "NC" at -129.2,1385 h40
  text "SCK" at 1958,1383 h45
  text "IOREF" at -189,1349 h40 r315
  text "D13" at 1962,1338 h35
  text "I2S_B" at 1693,1323 h40 r270
  text "MISO" at 1958,1290 h45
  text "NRST" at -188,1250 h40 r315
  text "D12" at 1962,1247 h35
  text "SDMMC" at 182.29,1240 h40 r270
  text "PWM" at 1958,1199 h45
  text "MOSI" at 1958,1164 h45
  text "3V3" at -157,1130 h40 r315
  text "D11" at 1962,1122 h35
  text "PWM" at 1958,1079 h45
  text "SPI_B" at 1681,1047 h40 r270
  text "CS" at 1958,1042 h45
  text "D10" at 1962,997 h35
  text "5V" at -129.01,982 h40
  text "PWM" at 1958,947 h45
  text "GND" at -159.72,919.13 h38 r315
  text "D9" at 1962,905 h35
  text "D8" at 1962,832 h40
  text "GND" at -160.72,817.25 h38 r315
  text "IO" at 198,766 h40 r270
  text "D7" at 1962,691 h40
  text "AVDD" at 1596,688 h40
  text "VIN" at -133.58,681 h40
  text "PWM" at 1958.06,622.84 h45
  text "AGND" at 1591.81,587 h40
  text "D6" at 1962,570 h40
  text "PWM" at 1958.06,512 h45
  text "GND" at 1631.61,486 h40
  text "A0" at -129.39,482 h40
  text "D5" at 1962,465 h40
  text "A1" at -112.25,390 h40
  text "USART" at 187,385 h40 r270
  text "D4" at 1962,381 h40
  text "ADC_IN" at 1667,330 h40 r270
  text "PWM" at 1958.06,311 h45
  text "A2" at -129.39,285 h40
  text "D3" at 1962,260 h40
  text "A3" at -129.39,189 h40
  text "D2" at 1962,180 h40
  text "TX" at 1958.06,118 h45
  text "A4" at -131.29,90 h40
  text "D1" at 1962,71 h40
  text "RX" at 1958.06,12.25 h45
  text "A5" at -129.39,-12 h40
  text "GND" at 164,-19 h40
  text "D0" at 1962,-37 h40
  text "COMP" at -142,-94 h40 r270
  text "QSPI" at 1657.48,-156 h40 r270
  text "SAI_A" at 187,-173 h40 r270
  text "I2C" at -128,-372 h40 r270
  text "TIMER" at 1998,-424 h40 r270
  text "SAI_B" at 193,-577 h40 r270
  text "GND" at -151,-579 h38 r315
  text "GND" at 1631.61,-617 h40
  text "CAN" at -148,-701 h40 r270
  text "MB1312A" at 444,-705.79 h40
  text "TIMER" at 1659.5,-730 h40 r270
  text "www.st.com/stm32nucleo" at 447,-790.79 h60
  text "IO" at -100.78,-926 h40
  text "IO" at 173,-928 h40
  text "GND" at -314,-1811 h50
  text "GND" at 2087,-1811 h50
  text "USER" at -190,-2164 h40
  text "RESET" at 1942,-2164 h40
  text "User USB" at 1185,-2182 h40
Bottom Overlay:
  drawing of 453 lines, arcs and shapes, not listed
  text "RESERVED" at 646,2974 h40
  text "DEFAULT" at 215,2972 h40
  text "JP1" at 993,2811 h40
  text "CN1" at 1517,2777 h40
  text "CN3" at 2255,2696 h40
  text "CN2" at -253,2688 h40
  text "SMD" at -175,2554.51 h40 r90
  text "CN4" at 342,2477 h40
  text "SWO" at 1229,2395 h40 r90
  text "MCO" at 1290,2395 h40 r90
  text "STLK_RST" at -177,2385 h36 r90
  text "NRST" at 222,2372 h40 r90
  text "MCU_RST" at 24,2349 h36 r90
  text "TX" at 457,2268 h40
  text "RST" at 224,2206 h40 r90
  text "RX" at 447,2179 h40
  text "JP3" at 141,2098 h40
  text "JP2" at -224,2097 h40
  text "CN5" at -52.49,2097 h40
  text "CN6" at 356,2096 h40
  text "CN11" at -169.49,1878 h40
  text "JP6" at 1605,1877 h40
  text "CN12" at 2231.51,1871 h40
  text "CN7" at 1823.51,1836 h40
  text "PC8" at 2312,1823 h28 r45
  text "PWR Source" at 1600,1818 h40
  text "PC11" at -52.49,1783 h28
  text "PC9" at 2051,1774 h28
  text "PC10" at -345,1732 h28 r315
  text "PC6" at 2318,1732 h28 r45
  text "JP5" at 1001,1715 h40
  text "PD2" at -70,1679 h28
  text "PB8" at 2051,1674 h28
  text "PC12" at -346,1646 h28 r315
  text "PC5" at 2319,1628 h28 r45
  text "JP4" at 536,1627 h40
  text "E5V" at -70,1577 h28
  text "PB9" at 2051,1574 h28
  text "VDD" at -362,1569 h28 r315
  text "VREF+" at 1991,1541 h28 r135
  text "U5V" at 2315,1523 h28 r45
  text "GND" at -70,1479 h28
  text "BT0" at -365,1474 h28 r315
  text "CN8" at 147.51,1467 h40
  text "PD8" at 2315,1426 h28 r45
  text "PF6" at -362,1374 h28 r315
  text "GND" at 2051,1374 h28
  text "NC" at -105,1373 h28
  text "PA12" at 2319,1310 h28 r45
  text "+3V3" at -44,1279 h28
  text "PA5" at 2051,1274 h28
  text "PF7" at -362,1270 h28 r315
  text "PA11" at 2308,1202 h28 r45
  text "PA6" at 2051,1174 h28
  text "NRST" at -46,1172 h28
  text "PA13" at -346,1143 h28 r315
  text "PB12" at 2312,1103 h28 r45
  text "3V3" at -70,1079 h28
  text "PA7" at 2051,1074 h28
  text "PA14" at -346,1042 h28 r315
  text "PB11" at 2314,1004 h28 r45
  text "+5V" at -70,977 h28
  text "PB6" at 2051,974 h28
  text "PA15" at -346,944 h28 r315
  text "GND" at 2319,923 h28 r45
  text "GND" at -70,880 h28
  text "PC7" at 2051,874 h28
  text "GND" at -362,873 h28 r315
  text "PB2" at 2314,823 h28 r45
  text "GND" at -70,780 h28
  text "PA9" at 2051,774 h28
  text "PB7" at -362,773 h28 r315
  text "PB1" at 2308,716 h28 r45
  text "VIN" at -76,675 h28
  text "PA8" at 2051,674 h28
  text "PC13" at -346,647 h28 r315
  text "PB15" at 2312,610 h28 r45
  text "PB10" at 2051,574 h28
  text "CN9" at 121.51,567 h40
  text "PC14" at -346,544 h28 r315
  text "PB14" at 2314,507 h28 r45
  text "PA0" at -70,481 h28
  text "PB4" at 2051,474 h28
  text "PC15" at -353,452 h28 r315
  text "PB13" at 2320,412 h28 r45
  text "PA1" at -82,379 h28
  text "PB5" at 2051,374 h28
  text "OSCI" at -346,345 h28 r315
  text "AGND" at 2322.6,320 h28 r45
  text "PA4" at -69.99,283 h28
  text "PB3" at 2051,274 h28
  text "OSCO" at -346,245 h28 r315
  text "MCO" at 1091,233 h40 r90
  text "PC4" at 2313,229 h28 r45
  text "PB0" at -70,179 h28
  text "PA10" at 2051,174 h28
  text "VBAT" at -346,144 h28 r315
  text "PF5" at 2317,121 h28 r45
  text "PC1" at -82,76 h28
  text "PA2" at 2051,74 h28
  text "PC2" at -362,62 h28 r315
  text "PF4" at 2315,25 h28 r45
  text "PC0" at -70,-22 h28
  text "PA3" at 2051,-26 h28
  text "PC3" at -362,-40 h28 r315
  text "PE8" at 2313,-80 h28 r45
  text "PD3" at -70,-123 h28
  text "GND" at 2051,-126 h28
  text "PD4" at -365,-128 h28 r315
  text "PF10" at 2323,-179 h28 r45
  text "PG2" at -70,-223 h28
  text "PD13" at 2051,-226 h28
  text "PD5" at -366,-227 h28 r315
  text "PE7" at 2315,-282 h28 r45
  text "PG3" at -70,-320 h28
  text "PD6" at -366,-326 h28 r315
  text "PD12" at 2051,-326 h28
  text "PD14" at 2321,-382 h28 r45
  text "PE2" at -70,-422 h28
  text "PD7" at -368,-423 h28 r315
  text "PD11" at 2051,-426 h28
  text "PD15" at 2315,-487 h28 r45
  text "PE4" at -69.99,-517 h28
  text "PE3" at -367,-525 h28 r315
  text "PE10" at 2051,-526 h28
  text "PF14" at 2317,-586 h28 r45
  text "GND" at -365,-621 h28 r315
  text "PE12" at 2051,-626 h28
  text "PE5" at -70,-628 h28
  text "PF1" at -364,-676 h28 r315
  text "PE9" at 2315,-682 h28 r45
  text "PF2" at -70,-722 h28
  text "PE14" at 2051,-726 h28
  text "PH1" at -362,-728 h28 r315
  text "PF0" at -367,-777 h28 r315
  text "GND" at 2315,-781 h28 r45
  text "PF8" at -70,-822 h28
  text "PE15" at 2051,-826 h28
  text "PH0" at -362,-848 h28 r315
  text "PE11" at 2320,-878 h28 r45
  text "PF9" at -70,-922 h28
  text "PD1" at -362,-925 h28 r315
  text "PE13" at 2051,-926 h28
  text "PF3" at 2318,-977 h28 r45
  text "CN10" at 1781.51,-1012 h40
  text "PD0" at -362,-1027 h28 r315
  text "PF13" at 2051,-1028 h28
  text "PG1" at -82,-1029 h28
  text "PF15" at 2321,-1085 h28 r45
  text "GND" at -70,-1122 h28
  text "PF12" at 2051,-1126 h28
  text "PG0" at -364,-1128 h28 r315
  text "PF11" at 2314,-1188 h28 r45
  text "PE6" at -70,-1223 h28
  text "PG14" at 2051,-1226 h28
  text "PE1" at -365,-1228 h28 r315
  text "PE0" at 2315,-1276 h28 r45
  text "PG15" at -40.83,-1317 h28
  text "GND" at 2051,-1326 h28
  text "PG9" at -364,-1330 h28 r315
  text "PG8" at 2313,-1380 h28 r45
  text "PG10" at -40.83,-1417 h28
  text "PD10" at 2051,-1426 h28
  text "PG12" at -346,-1457 h28 r315
  text "PG5" at 2319,-1472 h28 r45
  text "PG13" at -40.83,-1518 h28
  text "PG7" at 2051,-1526 h28
  text "PH2" at -362,-1527 h28 r315
  text "PG6" at 2318,-1571 h28 r45
  text "PG11" at -40.83,-1613 h28
  text "PG4" at 2051,-1626 h28
  text "PD9" at -362,-1630 h28 r315
  text "CN13" at 551.51,-1937 h40
  text "CN14" at 1350.51,-2176 h40
Mechanical 1:
  lines w5: -427.95,-2121.26 -427.95,2045.67 182.29,2045.66 ccw(c182.29,2065.35) 182.29,2085.03 -427.95,2085.03 -427.95,2970.86 cw(c-349.21,2970.86) -349.21,3049.6 2249.22,3049.6 cw(c2249.22,2970.86) 2327.96,2970.86 ; -427.8,-2121.22 ccw(c-349.06,-2121.22) -349.06,-2199.96 ; -349.21,-2200 2249.21,-2200 ; 2249.22,-2199.8 ccw(c2249.22,-2121.06) 2327.96,-2121.06 ; 2327.96,-2121.26 2327.96,2045.66 1698.03,2045.66 cw(c1698.03,2065.35) 1698.03,2085.03 2327.96,2085.03 2327.96,2970.86 ; 2327.96,2970.86 2327.96,2970.86 ; 320.08,2045.66 cw(c320.08,2065.35) 320.08,2085.03 1068.11,2085.03 cw(c1068.11,2065.35) 1068.11,2045.66 320.08,2045.66 ; 1250,2045.66 cw(c1250,2065.35) 1250,2085.03 1538.59,2085.03 cw(c1538.59,2065.35) 1538.59,2045.66 1250,2045.66
Drill Drawing:
  rectangle: 4947.07,1784.93 5591.07,1801.93
  rectangle: 4945.98,1419.52 5589.98,1436.52
  rectangle: 4947.83,2040.48 5591.83,2057.48
  rectangle: 4947.83,1900.41 5591.83,1917.41
  rectangle: 4947.83,1664.19 5591.83,1681.19
  rectangle: 4947.07,1548.71 5591.07,1565.71
  lines w5: -349.37,-2200.04 1040,-2200.04 1040,-1825.16 1598,-1825.16 1598,-2200.04 2249.06,-2200.04 ; -349.21,-2200 cw(c-349.21,-2121.26) -427.95,-2121.26 -427.95,2045.67 182.28,2045.67 ccw(c182.28,2065.35) 182.28,2085.04 -427.95,2085.04 -427.95,2970.87 cw(c-349.21,2970.87) -349.21,3049.61 2249.21,3049.61 cw(c2249.21,2970.87) 2327.95,2970.87 ; 2249.06,-2199.84 ccw(c2249.06,-2121.1) 2327.8,-2121.1 ; 2327.95,-2121.26 2327.95,2045.67 1698.03,2045.67 cw(c1698.03,2065.35) 1698.03,2085.04 2327.95,2085.04 2327.95,2970.87 ; 3861,3847 3881,3847 ; 2327.95,2970.87 2327.95,2970.87 ; 320.08,2045.67 cw(c320.08,2065.35) 320.08,2085.04 1068.11,2085.04 cw(c1068.11,2065.35) 1068.11,2045.67 320.08,2045.67 ; 1250,2045.67 cw(c1250,2065.35) 1250,2085.04 1538.58,2085.04 cw(c1538.58,2065.35) 1538.58,2045.67 1250,2045.67
  lines w7: 5130.43,1596.54 4992.43,1596.54 4992.43,1635.54 5169.43,1635.54 ; 5130.43,1832.76 4992.43,1832.76 4992.43,1871.76 5169.43,1871.76 ; 5169.43,1596.54 5346.43,1596.54 ; 5169.43,1832.76 5346.43,1832.76 ; 5228.43,1635.54 5366.43,1635.54 ; 5228.43,1871.76 5366.43,1871.76 ; 5386.43,1596.54 5543.43,1596.54 5543.43,1635.54 5425.43,1635.54 ; 5386.43,1832.76 5543.43,1832.76 5543.43,1871.76 5425.43,1871.76
  lines w8: 5012.94,1154.53 5590.08,1154.53 ; 5012.94,1237.03 5589.3,1237.03
  lines w10: 3606,3547 6001,3547 ; 3606,3647 5602,3647 6002,3647 6002,3648 ; 3606,3747 5602,3747 6002,3747 6002,3748 ; 4086,3449 4086,3847 ; 4166.24,2703.49 5829.24,2703.49 ; 4406,3449 4406,3847 ; 4806,3449 4806,3847 ; 4980.74,1956.48 5547.66,1956.48 ; 4980.74,2001.41 5547.66,2001.41 ; 4985.88,1706.84 5552.81,1706.84 ; 4985.88,1751.77 5552.81,1751.77 ; 4997.69,1474.55 5564.62,1474.55 ; 4997.69,1519.48 5564.62,1519.48 ; 5602,3449 3606,3449 3606,3847 5602,3847 ; 5602,3449 5602,3847 ; 5602,3449 6002,3449 6002,3847 5602,3847 ; 3514.92,951.02 6389.92,951.02 6389.92,2939.2 3514.92,2939.2 3514.92,951.02
  text "IMPEDANCE TABLE" at 3612,3909 h49.21
  text "LAYER" at 3685,3772 h49.21
  text "WIDTH" at 4143,3772 h49.21
  text "Clearance" at 4465,3772 h49.21
  text "TOLERANCE" at 5611,3771 h49.21
  text "Differential Impedence" at 4859,3769.66 h49.21
  text "Layer1,6" at 3685,3683 h49.21
  text "5.1mil" at 4132,3670 h49.21
  text "9.9mil" at 4512,3668 h49.21
  text "100 OHM" at 5004,3668 h49.21
  text "+/- 10%" at 5646,3668 h49.21
  text "Layer1,6" at 3685,3571.34 h49.21
  text "90 OHM" at 5011,3571.34 h49.21
  text "+/- 10%" at 5630,3571.34 h49.21
  text "6.1mil" at 4132,3569 h49.21
  text "8.9mil" at 4512,3569 h49.21
  text "MB1137 B" at -227,3077 h60
  text "LAYER STACK CONFIGURATION" at 4414.31,2737.68 h49.21
  text "6 LAYER BUILD" at 4602.95,2453.99 h49.21
  text "0.7mil" at 5839.25,2034.72 h39.37
  text "TOP LAYER" at 4215.1,2017.94 h49.21
  text "4mil" at 5621.18,1960.86 h39.37
  text "1.4mil" at 5839.25,1892.98 h39.37
  text "GND" at 4215.1,1885 h49.21
  text "13mil" at 5621.18,1833.93 h39.37
  text "MID LAYER 1" at 4215.1,1768.89 h49.21
  text "1.4mil" at 5837.72,1765.98 h39.37
  text "16.5mil" at 5621.18,1712.83 h39.37
  text "1.4mil" at 5839.69,1653.77 h39.37
  text "PWR" at 4215.1,1647.87 h49.21
  text "13mil" at 5621.18,1598.65 h39.37
  text "1.4mil" at 5839.69,1541.57 h39.37
  text "GND" at 4215.1,1537.63 h49.21
  text "4mil" at 5621.18,1478.57 h39.37
  text "0.7mil" at 5839.69,1417.55 h39.37
  text "BOTTOM LAYER" at 4215.1,1405.74 h49.21
  text "63mil" at 5068.87,1178.78 h49.21
  text "(plus soldermask thickness)" at 5400.71,1173.46 h49.21
  text "TOTAL BOARD THICKNESS: APPROX" at 3787.77,1172.91 h49.21
  text "Notes" at 4772.78,801.28 h49.21
  text "Silkscreen color : Blue ink PANTONE 2955" at 4987,681 h49.21
  text "Solder resist color : White" at 4991,596 h49.21
  text ".Legend" at 3703.99,-1199 h60

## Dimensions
-427.95,-2121.26 to 2327.95,-2121.26 on Drill Drawing
2249.21,3049.61 to 2249.06,-2200.04 on Drill Drawing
